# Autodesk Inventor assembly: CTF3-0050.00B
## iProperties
Shininess: 64.0
Length Units: 11269
Angle Units: 11279
Time Units: 11290
Mass Units: 11283
Length Display Precision: 3
Angle Display Precision: 2
Compacted: True
Created: 2003-11
Part Number: CTF3-0050.00B
Document SubType Name: Assembly
Designer: Lollo
Density: 0.0
Volumn: 0.0
Area: 0.0
PropertySet Name: Model Information
Control State: 0
Master: False
Checked Out: False
Author: Lollo
